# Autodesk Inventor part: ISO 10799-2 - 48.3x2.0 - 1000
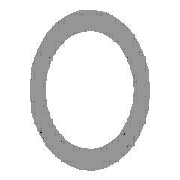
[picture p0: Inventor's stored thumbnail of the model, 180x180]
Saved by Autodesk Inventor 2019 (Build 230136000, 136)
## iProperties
IsCustomPart: 1
Created: 2018-07
Part Number: ISO 10799-2 - 48.3x2.0 - 1000
Material: Acier, doux
Description: Aciers de construction - Coupes creuses profilées formées à froid, soudées
Document SubType Name: Modeling
Standard: ISO
Designer: Fabian Perrée
Standard Revision: First edition 2011-09-15
Standards Organization: ISO
Language: fr-FR
Size Designation: 48.3x2.0
Categories: <MemberInstance><Categories><Category DisplayName="Profilés" InternalName="089c4875-fa83-4c05-b084-43b9cc11f5ed" Mnemonic="GRDR"><CategoryParameter DisplayName=
Stock Number: 48.3x2.0
Density: 7.85 g/cm^3
Appearance: Semi-poli
Mass: 2283.66 g
Surface Area: 2914.93 cm^2
Volume: 290.911 cm^3
_CCFamilyMember: 14
_CCFamilyDisplayName: ISO 10799-2 (Profils creux circulaires - Formés à froid) - Aciers de construction - Coupes creuses profilées formées à froid, soudées
_FrameMemberDoc: Frame Member File
_Version: 15.0.0
_GetPNFromCC: 1
G_L: 1000,000 mm
G_W: 48,300 mm
G_H: 48,300 mm
Author: Fabian Perrée
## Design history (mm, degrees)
node "Plan de départ"
node "Plan de fin"
sketch "Esquisse"
  geometry: C1 r 22.15 at (0, 0); C2 r 24.15 at (0, 0); 2 further points
  constraints: 3 coincident, 2 centre point
  dimensions: "d0" = 48.3 diameter of C2 (= G_H); "d1" = 2 radial gap between concentric circles of C2 C1 (= G_T)
extrude "Corps" new body sketch "Esquisse" stored distance "d2" = 1000 (= G_L); taper "d3" = 0 deg
node "Driven Length"
  sketch "Sketch3"
    geometry: L1 (0, 0)-(10, 0) reference
    constraints: 2 end point, 1 horizontal
  workplane "Work Plane3"
  sketch "Sketch4"
    geometry: L1 (-2, 0)-(12, 0) reference; L2 (-2, 1000)-(12, 1000) reference
    dimensions: "d7" = 1000 distance between parallel lines of L1 L2 (derived)
body "Solid1"
other parameters: "G_H" = 48.3 [user parameter; used in 1 equation term], "G_T" = 2 [user parameter; used in 1 equation term], "G_L" = 1000 (= d7) [user parameter; used in 1 equation term], "G_OFFSET_START" = 0 [user parameter; used in 1 equation term], "G_OFFSET_END" = 0 [user parameter; used in 1 equation term], "d4" = 0 (computed from G_OFFSET_START), "d6" = 90 deg, "MAS" = 0.228 [user parameter]
